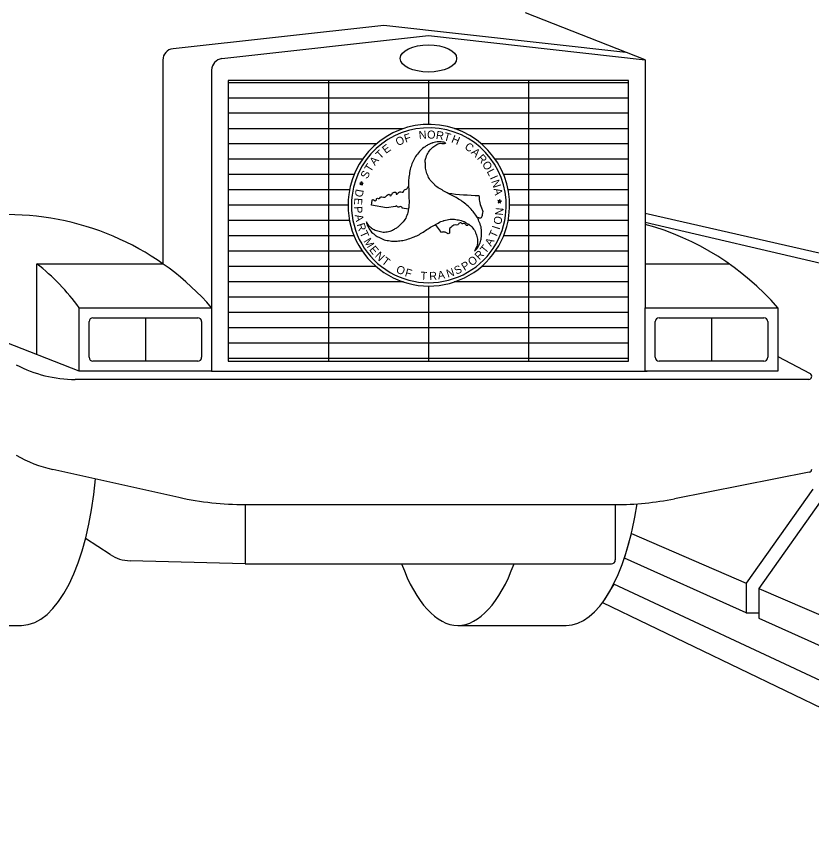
# Model space of a CAD drawing. Extents: x 2141134 to 2191774, y 803576 to 836576.
# Drawn here: x 2150916 to 2152118, y 805488 to 806717 of the extents above; entities that cross this region are included whole.
import ezdxf

# ---------------------------------------------------------------- set-up
doc = ezdxf.new("R2010")
doc.units = 0
doc.layers.add('Exist Road Secondary Type 20 SR Number Label', color=7, linetype='Continuous')

msp = doc.modelspace()

# ---------------------------------------------------------------- linework, layer by layer
at = {"layer": 'Exist Road Secondary Type 20 SR Number Label'}
for p, q in [((2151866.5, 806651.2), (2151685.6, 806722.2)), ((2151153, 806668), (2151471.7, 806703.6)), ((2151471.7, 806703.6), (2151837, 806662.8)), ((2151137.6, 806650.7), (2151137.6, 806343)), ((2151866.5, 806651.2), (2151866.5, 806276.5)), ((2151211.3, 806635.6), (2151211.3, 806276.5)), ((2151841.4, 806616.6), (2151236.4, 806616.6)), ((2151387.7, 806620), (2151387.7, 806195.9)), ((2151538.9, 806620), (2151538.9, 806553.5)), ((2151690.2, 806620), (2151690.2, 806195.9)), ((2151841.4, 806593.4), (2151236.4, 806593.4)), ((2151841.4, 806570.3), (2151236.4, 806570.3)), ((2151500.6, 806547.1), (2151236.4, 806547.1)), ((2151841.4, 806547.1), (2151578.5, 806547.1)), ((2151459.9, 806524), (2151236.4, 806524)), ((2151565.1, 806525.6), (2151564.9, 806525.4)), ((2151565.1, 806525.6), (2151564.9, 806525.4)), ((2151565.1, 806525.6), (2151564.9, 806525.4)), ((2151841.4, 806524), (2151619.2, 806524)), ((2151439.1, 806500.8), (2151236.4, 806500.8)), ((2151841.4, 806500.8), (2151640, 806500.8)), ((2151426.6, 806477.7), (2151236.4, 806477.7)), ((2151841.4, 806477.7), (2151652.5, 806477.7)), ((2151436.6, 806464), (2151435, 806465.5)), ((2151435, 806465.5), (2151437.2, 806465.2)), ((2151436.6, 806464), (2151435, 806465.5)), ((2151435, 806465.5), (2151437.2, 806465.2)), ((2151435.7, 806462.1), (2151436.6, 806464)), ((2151435.7, 806462.1), (2151436.6, 806464)), ((2151437.5, 806463.1), (2151435.7, 806462.1)), ((2151437.5, 806463.1), (2151435.7, 806462.1)), ((2151437.2, 806465.2), (2151438, 806467.1)), ((2151437.2, 806465.2), (2151438, 806467.1)), ((2151439, 806461.6), (2151437.5, 806463.1)), ((2151439, 806461.6), (2151437.5, 806463.1)), ((2151438, 806467.1), (2151438.4, 806465)), ((2151438, 806467.1), (2151438.4, 806465)), ((2151438.4, 806465), (2151440.5, 806464.8)), ((2151438.4, 806465), (2151440.5, 806464.8)), ((2151440.5, 806464.8), (2151438.6, 806463.7)), ((2151440.5, 806464.8), (2151438.6, 806463.7)), ((2151438.6, 806463.7), (2151439, 806461.6)), ((2151438.6, 806463.7), (2151439, 806461.6)), ((2151419.7, 806454.5), (2151236.4, 806454.5)), ((2151841.4, 806454.5), (2151659.4, 806454.5)), ((2151452.8, 806431.4), (2151454, 806438.7)), ((2151452.8, 806431.4), (2151454, 806438.7)), ((2151568.2, 806449.6), (2151568.2, 806449.6)), ((2151568.2, 806449.6), (2151568.2, 806449.6)), ((2151645.7, 806438.2), (2151643.6, 806438.4)), ((2151643.6, 806438.4), (2151645.2, 806437)), ((2151645.7, 806438.2), (2151643.6, 806438.4)), ((2151643.6, 806438.4), (2151645.2, 806437)), ((2151646.6, 806440), (2151645.7, 806438.2)), ((2151646.6, 806440), (2151645.7, 806438.2)), ((2151647, 806438), (2151646.6, 806440)), ((2151647, 806438), (2151646.6, 806440)), ((2151649.1, 806437.8), (2151647, 806438)), ((2151649.1, 806437.8), (2151647, 806438)), ((2151647.2, 806436.7), (2151649.1, 806437.8)), ((2151647.2, 806436.7), (2151649.1, 806437.8)), ((2151417.5, 806431.4), (2151236.4, 806431.4)), ((2151475.6, 806427.5), (2151452.8, 806431.4)), ((2151475.6, 806427.5), (2151452.8, 806431.4)), ((2151489.3, 806429.6), (2151475.6, 806427.5)), ((2151489.3, 806429.6), (2151475.6, 806427.5)), ((2151508.8, 806425.4), (2151499.2, 806426.8)), ((2151508.8, 806425.4), (2151499.2, 806426.8)), ((2151645.2, 806437), (2151644.3, 806435.1)), ((2151645.2, 806437), (2151644.3, 806435.1)), ((2151644.3, 806435.1), (2151646.1, 806436.1)), ((2151644.3, 806435.1), (2151646.1, 806436.1)), ((2151646.1, 806436.1), (2151647.6, 806434.6)), ((2151646.1, 806436.1), (2151647.6, 806434.6)), ((2151647.6, 806434.6), (2151647.2, 806436.7)), ((2151647.6, 806434.6), (2151647.2, 806436.7)), ((2151841.4, 806431.4), (2151661.6, 806431.4)), ((2151660.5, 806415.4), (2151660.5, 806415.4)), ((2151660.5, 806415.4), (2151660.5, 806415.4)), ((2151866.5, 806419.4), (2152227.9, 806337.1)), ((2151419.7, 806408.2), (2151236.4, 806408.2)), ((2151558.5, 806390.2), (2151549.8, 806402.5)), ((2151549.8, 806402.5), (2151549.8, 806402.5)), ((2151558.5, 806390.2), (2151549.8, 806402.5)), ((2151549.8, 806402.5), (2151549.8, 806402.5)), ((2151841.4, 806408.2), (2151659.4, 806408.2)), ((2152158, 806337.1), (2151866.5, 806405.2)), ((2151426.6, 806385.1), (2151236.4, 806385.1)), ((2151841.4, 806385.1), (2151652.4, 806385.1)), ((2151439.2, 806361.9), (2151236.4, 806361.9)), ((2151841.4, 806361.9), (2151639.9, 806361.9)), ((2150947.2, 806205.8), (2150947.2, 806343)), ((2150947.2, 806343), (2151137.6, 806343)), ((2151866.5, 806343), (2151993, 806343)), ((2151460.1, 806338.7), (2151236.4, 806338.7)), ((2151841.4, 806338.7), (2151618.9, 806338.7)), ((2151501.1, 806315.6), (2151236.4, 806315.6)), ((2151841.4, 806315.6), (2151578, 806315.6)), ((2151538.9, 806309.4), (2151538.9, 806195.9)), ((2151841.4, 806292.4), (2151236.4, 806292.4)), ((2151841.4, 806269.3), (2151236.4, 806269.3)), ((2151026.1, 806201.7), (2151026.1, 806255.7)), ((2151031.9, 806261.5), (2151190.4, 806261.5)), ((2151111.2, 806261.5), (2151111.2, 806195.9)), ((2151196.2, 806255.7), (2151196.2, 806201.7)), ((2151881.6, 806201.7), (2151881.6, 806255.7)), ((2151887.4, 806261.5), (2152045.9, 806261.5)), ((2151966.6, 806261.5), (2151966.6, 806195.9)), ((2152051.7, 806255.7), (2152051.7, 806201.7)), ((2151011.1, 806180.8), (2150853.1, 806242.6)), ((2151841.4, 806246.1), (2151236.4, 806246.1)), ((2151841.4, 806223), (2151236.4, 806223)), ((2151190.4, 806195.9), (2151031.9, 806195.9)), ((2151841.4, 806199.8), (2151236.4, 806199.8)), ((2152045.9, 806195.9), (2151887.4, 806195.9)), ((2152066.8, 806202.8), (2152115.7, 806177)), ((2151211.3, 806180.8), (2151869.4, 806180.8)), ((2151161.8, 805990.1), (2150971.1, 806032.4)), ((2152114.4, 806028.1), (2151910.9, 805987.9)), ((2152119.6, 806002.3), (2152019.1, 805860.6)), ((2152139.2, 805995.2), (2152038, 805852.5)), ((2151262, 805979.2), (2151262, 805889.7)), ((2151262, 805979.2), (2151821.3, 805979.2)), ((2151821.3, 805979.2), (2151821.3, 805895.5)), ((2151835, 805898.2), (2151845.6, 805935.3)), ((2151845.6, 805935.3), (2152019.1, 805860.6)), ((2151057.8, 805903.8), (2151020.8, 805928.1)), ((2152019.1, 805815.8), (2151835, 805898.2)), ((2151262, 805889.7), (2151088.1, 805894.3)), ((2151262, 805889.7), (2151815.5, 805889.7)), ((2152019.1, 805860.6), (2152019.1, 805815.8)), ((2151818.9, 805859.1), (2151802, 805831.3)), ((2152614, 805488), (2151818.9, 805859.1)), ((2152038, 805852.5), (2152038, 805807.4)), ((2152038, 805852.5), (2152879.1, 805490.7)), ((2151802, 805831.3), (2152514.5, 805488)), ((2152019.1, 805815.8), (2152038, 805815.8)), ((2152038, 805807.4), (2152752, 805488)), ((2150760.3, 805796.7), (2150924.1, 805796.7)), ((2151583.3, 805796.7), (2151747.1, 805796.7))]:
    msp.add_line(p, q, dxfattribs=at)
for points in [[(2151226.7, 806652.9), (2151538.9, 806687.8), (2151866.5, 806651.2)], [(2152113.5, 806168.2), (2151005.1, 806168.2)]]:
    msp.add_lwpolyline(points, dxfattribs=at)
for points in [[(2151236.4, 806195.9), (2151841.4, 806195.9), (2151841.4, 806620), (2151236.4, 806620)], [(2151211.3, 806180.8), (2151011.1, 806180.8), (2151011.1, 806276.5), (2151211.3, 806276.5)], [(2152066.8, 806180.8), (2151866.5, 806180.8), (2151866.5, 806276.5), (2152066.8, 806276.5)]]:
    msp.add_lwpolyline(points, close=True, dxfattribs=at)
for centre, radius, start, end in [((2151154.9, 806650.7), 17.4, 96.3744, 180), ((2151228.7, 806635.6), 17.4, 96.3744, 180), ((2151539.5, 806431.4), 122.1, 352.4211, 172.4211), ((2151539.5, 806431.4), 122.1, 352.4211, 172.4211), ((2151539.5, 806431.4), 117, 352.4211, 172.4211), ((2151539.5, 806431.4), 117, 352.4211, 172.4211), ((2151640.6, 807089.1), 643.6, 258.0996, 258.1992), ((2151640.6, 807089.1), 643.6, 258.0996, 258.1992), ((2151539.5, 806431.4), 122.1, 172.4211, 352.4211), ((2151539.5, 806431.4), 122.1, 172.4211, 352.4211), ((2151539.5, 806431.4), 117, 172.4211, 352.4211), ((2151539.5, 806431.4), 117, 172.4211, 352.4211), ((2151640.6, 807089.1), 643.6, 263.5387, 267.7447), ((2151640.6, 807089.1), 643.6, 263.5387, 267.7447), ((2150902.7, 806008.2), 409, 41.0136, 90), ((2151758.2, 806008.2), 409, 41.0136, 74.6352), ((2150731.4, 806071.7), 346.7, 36.2283, 51.4998), ((2151031.9, 806255.7), 5.79, 90, 180), ((2151190.4, 806255.7), 5.79, 0, 90), ((2151887.4, 806255.7), 5.79, 90, 180), ((2152045.9, 806255.7), 5.79, 0, 90), ((2151031.9, 806201.7), 5.79, 180, 270), ((2151190.4, 806201.7), 5.79, 270, 0), ((2151887.4, 806201.7), 5.79, 180, 270), ((2152045.9, 806201.7), 5.79, 270, 0), ((2151005.1, 806359.2), 190.9, 242.1887, 270), ((2152113.5, 806172.9), 4.63, 270, 62.1886), ((2151012.9, 806220.8), 193, 239.8868, 257.5069), ((2152113.5, 806032.6), 4.63, 281.1571, 0), ((2151262, 806442.3), 463.1, 257.5069, 270), ((2151821.3, 806442.3), 463.1, 270, 281.1571), ((2151089.6, 805952.1), 57.9, 236.6718, 268.5078), ((2151815.5, 805895.5), 5.79, 270, 0)]:
    msp.add_arc(centre, radius, start, end, dxfattribs=at)
msp.add_ellipse((2151538.9, 806653.3), major_axis=(-42.6, 0), ratio=0.48463, dxfattribs=at)
for centre, start_param, end_param in [((2150924.1, 806077.1), 3.141593, 4.500187), ((2151747.1, 806077.1), 3.141593, 4.359994), ((2151583.3, 806077.1), 2.302633, 3.980552)]:
    msp.add_ellipse(centre, major_axis=(0, 280.4), ratio=0.407167, start_param=start_param, end_param=end_param, dxfattribs=at)
for points in [[(2151564.9, 806525.4), (2151562.2, 806526.5), (2151554.2, 806527.2), (2151545.6, 806525.7), (2151544.9, 806525.4), (2151540.5, 806523.8), (2151535.7, 806521.1), (2151528.3, 806515.8), (2151522.3, 806508.8), (2151519.9, 806505.8), (2151517.9, 806502), (2151514, 806493.8), (2151511.5, 806485.8), (2151509.7, 806476.2), (2151508.7, 806467.7), (2151509, 806458.9), (2151509.3, 806449.9), (2151509.5, 806441.3), (2151509.5, 806432.4), (2151508.4, 806423.8), (2151508.2, 806423), (2151505.5, 806414), (2151500.7, 806406.5), (2151494.9, 806400.3), (2151491.7, 806397.6), (2151487.2, 806395), (2151484.7, 806393.4), (2151478.8, 806391.4), (2151470.3, 806390.5), (2151462.2, 806392.1), (2151455.3, 806394.9), (2151449.5, 806399.8), (2151445.3, 806406.2)], [(2151564.9, 806525.4), (2151562.2, 806526.5), (2151554.2, 806527.2), (2151545.6, 806525.7), (2151544.9, 806525.4), (2151540.5, 806523.8), (2151535.7, 806521.1), (2151528.3, 806515.8), (2151522.3, 806508.8), (2151519.9, 806505.8), (2151517.9, 806502), (2151514, 806493.8), (2151511.5, 806485.8), (2151509.7, 806476.2), (2151508.7, 806467.7), (2151509, 806458.9), (2151509.3, 806449.9), (2151509.5, 806441.3), (2151509.5, 806432.4), (2151508.4, 806423.8), (2151508.2, 806423), (2151505.5, 806414), (2151500.7, 806406.5), (2151494.9, 806400.3), (2151491.7, 806397.6), (2151487.2, 806395), (2151484.7, 806393.4), (2151478.8, 806391.4), (2151470.3, 806390.5), (2151462.2, 806392.1), (2151455.3, 806394.9), (2151449.5, 806399.8), (2151445.3, 806406.2)], [(2151608.4, 806362.3), (2151610.5, 806364), (2151615.2, 806370.6), (2151618.2, 806378.8), (2151618.4, 806379.6), (2151619.1, 806384.2), (2151619.2, 806389.7), (2151618.4, 806398.8), (2151615.2, 806407.4), (2151613.9, 806411.1), (2151611.6, 806414.8), (2151606.4, 806422.1), (2151600.7, 806428.3), (2151593.3, 806434.6), (2151586.4, 806439.7), (2151578.6, 806444), (2151570.8, 806448.1), (2151563.3, 806452.3), (2151555.5, 806456.8), (2151548.6, 806462), (2151548.1, 806462.6), (2151541.6, 806469.5), (2151537.4, 806477.5), (2151534.9, 806485.4), (2151534.3, 806489.5), (2151534.3, 806494.8), (2151534.1, 806497.8), (2151535.4, 806503.8), (2151538.9, 806511.7), (2151544.2, 806517.8), (2151550.1, 806522.4), (2151557.3, 806525), (2151564.9, 806525.4), (2151565.1, 806525.6)], [(2151608.4, 806362.3), (2151610.5, 806364), (2151615.2, 806370.6), (2151618.2, 806378.8), (2151618.4, 806379.6), (2151619.1, 806384.2), (2151619.2, 806389.7), (2151618.4, 806398.8), (2151615.2, 806407.4), (2151613.9, 806411.1), (2151611.6, 806414.8), (2151606.4, 806422.1), (2151600.7, 806428.3), (2151593.3, 806434.6), (2151586.4, 806439.7), (2151578.6, 806444), (2151570.8, 806448.1), (2151563.3, 806452.3), (2151555.5, 806456.8), (2151548.6, 806462), (2151548.1, 806462.6), (2151541.6, 806469.5), (2151537.4, 806477.5), (2151534.9, 806485.4), (2151534.3, 806489.5), (2151534.3, 806494.8), (2151534.1, 806497.8), (2151535.4, 806503.8), (2151538.9, 806511.7), (2151544.2, 806517.8), (2151550.1, 806522.4), (2151557.3, 806525), (2151564.9, 806525.4), (2151565.1, 806525.6)], [(2151454, 806438.7), (2151453.8, 806439.4), (2151455.1, 806440), (2151458.4, 806438.2), (2151460.3, 806439.4), (2151460.4, 806440.9), (2151462, 806442.2), (2151464.2, 806441.4), (2151466.7, 806443.8), (2151468.7, 806444), (2151472.8, 806443.5), (2151478.3, 806447.7), (2151480.4, 806447.7), (2151480.7, 806446.3), (2151481.9, 806445.9), (2151484.5, 806449.7), (2151485.2, 806450.2), (2151489.2, 806451.2), (2151490.1, 806450.3), (2151490.1, 806448.5), (2151490.6, 806448.1), (2151492, 806448.8), (2151493.9, 806450.7), (2151497.3, 806451.9), (2151500.8, 806451), (2151501.8, 806453.8), (2151506.3, 806456.1), (2151507.4, 806457.7), (2151507.8, 806459.3)], [(2151454, 806438.7), (2151453.8, 806439.4), (2151455.1, 806440), (2151458.4, 806438.2), (2151460.3, 806439.4), (2151460.4, 806440.9), (2151462, 806442.2), (2151464.2, 806441.4), (2151466.7, 806443.8), (2151468.7, 806444), (2151472.8, 806443.5), (2151478.3, 806447.7), (2151480.4, 806447.7), (2151480.7, 806446.3), (2151481.9, 806445.9), (2151484.5, 806449.7), (2151485.2, 806450.2), (2151489.2, 806451.2), (2151490.1, 806450.3), (2151490.1, 806448.5), (2151490.6, 806448.1), (2151492, 806448.8), (2151493.9, 806450.7), (2151497.3, 806451.9), (2151500.8, 806451), (2151501.8, 806453.8), (2151506.3, 806456.1), (2151507.4, 806457.7), (2151507.8, 806459.3)], [(2151509, 806459.1), (2151509, 806458.9), (2151509.3, 806449.9), (2151509.5, 806441.3), (2151509.5, 806432.4), (2151508.7, 806425.4)], [(2151509, 806459.1), (2151509, 806458.9), (2151509.3, 806449.9), (2151509.5, 806441.3), (2151509.5, 806432.4), (2151508.7, 806425.4)], [(2151613.2, 806412.5), (2151611.6, 806414.8), (2151606.4, 806422.1), (2151600.7, 806428.3), (2151593.3, 806434.6), (2151586.4, 806439.7), (2151578.6, 806444), (2151570.8, 806448.1), (2151568.2, 806449.6)], [(2151613.2, 806412.5), (2151611.6, 806414.8), (2151606.4, 806422.1), (2151600.7, 806428.3), (2151593.3, 806434.6), (2151586.4, 806439.7), (2151578.6, 806444), (2151570.8, 806448.1), (2151568.2, 806449.6)], [(2151615.3, 806446), (2151615.9, 806437.7), (2151618.9, 806427.6), (2151620.9, 806422), (2151620.2, 806417.6), (2151618.5, 806412.4), (2151613.3, 806412.5)], [(2151615.3, 806446), (2151615.9, 806437.7), (2151618.9, 806427.6), (2151620.9, 806422), (2151620.2, 806417.6), (2151618.5, 806412.4), (2151613.3, 806412.5)], [(2151499.2, 806426.8), (2151498.5, 806428.7), (2151496.7, 806429.4), (2151494, 806428.4), (2151492.1, 806428.8), (2151490.2, 806430.6), (2151489.3, 806429.6)], [(2151499.2, 806426.8), (2151498.5, 806428.7), (2151496.7, 806429.4), (2151494, 806428.4), (2151492.1, 806428.8), (2151490.2, 806430.6), (2151489.3, 806429.6)], [(2151445.3, 806406.2), (2151445.8, 806403.4), (2151449.2, 806396), (2151454.7, 806389.4), (2151455.4, 806388.9), (2151459, 806385.8), (2151463.7, 806383.1), (2151472, 806379.3), (2151481, 806377.7), (2151484.8, 806377), (2151489.3, 806377.2), (2151498.1, 806378), (2151506.3, 806379.8), (2151515.6, 806383), (2151523.3, 806386.4), (2151530.9, 806391), (2151538.4, 806395.9), (2151545.9, 806400.2), (2151553.6, 806404.6), (2151561.6, 806408.1), (2151562.5, 806408.3), (2151571.7, 806410.4), (2151580.5, 806410), (2151588.6, 806408.2), (2151592.7, 806406.8), (2151597.1, 806404.1), (2151599.9, 806402.8), (2151604.5, 806398.7), (2151609.4, 806391.7), (2151612.1, 806384), (2151613.2, 806376.6), (2151611.8, 806369.1), (2151608.4, 806362.3)], [(2151445.3, 806406.2), (2151445.8, 806403.4), (2151449.2, 806396), (2151454.7, 806389.4), (2151455.4, 806388.9), (2151459, 806385.8), (2151463.7, 806383.1), (2151472, 806379.3), (2151481, 806377.7), (2151484.8, 806377), (2151489.3, 806377.2), (2151498.1, 806378), (2151506.3, 806379.8), (2151515.6, 806383), (2151523.3, 806386.4), (2151530.9, 806391), (2151538.4, 806395.9), (2151545.9, 806400.2), (2151553.6, 806404.6), (2151561.6, 806408.1), (2151562.5, 806408.3), (2151571.7, 806410.4), (2151580.5, 806410), (2151588.6, 806408.2), (2151592.7, 806406.8), (2151597.1, 806404.1), (2151599.9, 806402.8), (2151604.5, 806398.7), (2151609.4, 806391.7), (2151612.1, 806384), (2151613.2, 806376.6), (2151611.8, 806369.1), (2151608.4, 806362.3)], [(2151549.8, 806402.5), (2151553.6, 806404.6), (2151561.6, 806408.1), (2151562.5, 806408.3), (2151571.7, 806410.4), (2151580.5, 806410), (2151588.6, 806408.2), (2151592.7, 806406.8), (2151597.1, 806404.1), (2151599.7, 806402.8)], [(2151549.8, 806402.5), (2151553.6, 806404.6), (2151561.6, 806408.1), (2151562.5, 806408.3), (2151571.7, 806410.4), (2151580.5, 806410), (2151588.6, 806408.2), (2151592.7, 806406.8), (2151597.1, 806404.1), (2151599.7, 806402.8)], [(2151599.6, 806402.8), (2151598.2, 806400.8), (2151596.4, 806400.9), (2151593.5, 806403.9), (2151589.5, 806403.6), (2151587.9, 806404.9), (2151586.7, 806405.1), (2151583.4, 806401.9), (2151579.4, 806401.6), (2151572.5, 806397.8), (2151570.8, 806395.3), (2151570.5, 806389.4), (2151568.8, 806388.4), (2151567, 806389), (2151563.3, 806391), (2151558.5, 806390.2)], [(2151599.6, 806402.8), (2151598.2, 806400.8), (2151596.4, 806400.9), (2151593.5, 806403.9), (2151589.5, 806403.6), (2151587.9, 806404.9), (2151586.7, 806405.1), (2151583.4, 806401.9), (2151579.4, 806401.6), (2151572.5, 806397.8), (2151570.8, 806395.3), (2151570.5, 806389.4), (2151568.8, 806388.4), (2151567, 806389), (2151563.3, 806391), (2151558.5, 806390.2)]]:
    msp.add_spline(points, degree=3, dxfattribs=at)

# ---------------------------------------------------------------- texts
for s, height, rotation, p in [('F', 12.2, 17.4918, (2151504.3, 806525.9)), ('N', 12.2, 5.4049, (2151524.8, 806531.2)), ('O', 12.2, 357.9068, (2151536.7, 806532.3)), ('R', 12.2, 351.2969, (2151549.6, 806531.8)), ('T', 12.2, 344.6472, (2151561.1, 806530)), ('H', 12.2, 337.5625, (2151572.5, 806526.8)), ('E', 12.1, 36.5781, (2151474.6, 806508.7)), ('O', 12.2, 24.6387, (2151492.6, 806520.6)), ('C', 12.1, 325.2202, (2151592.5, 806517.4)), ('T', 12.1, 43.6937, (2151466, 806500.5)), ('A', 12.2, 317.7231, (2151602.4, 806510.4)), ('A', 12.2, 50.7489, (2151458, 806490.7)), ('R', 12.2, 311.3592, (2151611.7, 806502)), ('T', 12.2, 57.8012, (2151451.6, 806480.7)), ('O', 12.2, 304.2396, (2151619.3, 806493.2)), ('L', 12.1, 298.0059, (2151626.6, 806482.5)), ('S', 12.2, 64.1774, (2151446.5, 806470.3)), ('I', 12.2, 294.0166, (2151631.4, 806473.1)), ('N', 12.2, 288.3165, (2151633.7, 806467.7)), ('D', 12.2, 260.2741, (2151429.3, 806456.5)), ('A', 12.2, 280.8845, (2151637.4, 806456.3)), ('E', 12.1, 266.562, (2151427.1, 806442.8)), ('P', 12.2, 274.0944, (2151426.5, 806429.5)), ('N', 12.2, 84.6293, (2151651.6, 806415.5)), ('A', 12.2, 280.687, (2151427.5, 806416.6)), ('O', 12.1, 77.3812, (2151648.5, 806401.2)), ('R', 12.2, 287.7556, (2151430.3, 806402.4)), ('T', 12.2, 294.4062, (2151434.5, 806389.7)), ('T', 12.2, 66.5957, (2151640.8, 806381.1)), ('I', 12.2, 72.2456, (2151646.2, 806393.7)), ('M', 12.1, 301.6412, (2151440.4, 806377.2)), ('A', 12.2, 59.5113, (2151633.6, 806368.5)), ('E', 12.1, 309.108, (2151448.7, 806364.1)), ('T', 12.1, 51.4242, (2151625.2, 806357.6)), ('N', 12.2, 316.0795, (2151457.1, 806354)), ('T', 12.2, 322.9215, (2151467.1, 806344.6)), ('O', 12.2, 38.1354, (2151604.4, 806338.8)), ('R', 12.2, 45.3245, (2151615.9, 806347.9)), ('O', 12.2, 336.2252, (2151488.8, 806330.4)), ('S', 12.1, 24.2515, (2151581, 806326.3)), ('P', 12.2, 31.4434, (2151593.3, 806331.9)), ('F', 12.2, 343.3904, (2151502.4, 806324.6)), ('T', 12.1, 356.2997, (2151526.7, 806319.1)), ('R', 12.2, 3.2563, (2151540.4, 806318.3)), ('A', 12.1, 10.0094, (2151553.8, 806319.3)), ('N', 12.1, 17.041, (2151568, 806322))]:
    msp.add_text(s, height=height, rotation=rotation, dxfattribs=at).set_placement(p)

doc.saveas('drawing.dxf')
